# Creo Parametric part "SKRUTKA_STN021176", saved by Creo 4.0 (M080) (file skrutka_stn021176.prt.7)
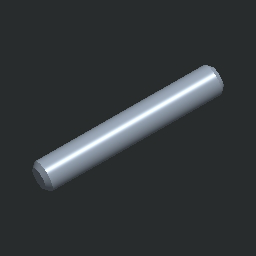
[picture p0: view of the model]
Units: millimeter Kilogram Sec (mmKs); MM, KILOGRAM, SECS
Materials in the file: OCEL_N

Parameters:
  MFG_WP_MATERIAL = "OCEL"
  NAZOV = "SKRUTKA_STN021176"
  NORMA = "STN 02 1176"
  PTC_MATERIAL_NAME = "OCEL_N"

Other parameters: HMOTNOST, HUSTOTA, D24, D14, D20

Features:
  1. datum plane "DTM2"
  2. protrusion
  3. chamfer

Other named items: BLIND, BLIND_1

Named dimensions: ezav

Layers: 1, 2, 3, 4, 5, 6, 7, 8, 9, 10, 11, 12, 13, 14, 15, 16, 17, 18, 19, 20, 21, 22, 23, 24, 25, 26, 27, 28, 29, 30, 31, 32

Family table entries: GENERIC, SKRUTKA_M3, SKRUTKA_STN021176, value(d_val), value(i_val), SKRUTKA_M4, SKRUTKA_STN021176, SKRUTKA_M5, SKRUTKA_STN021176, SKRUTKA_M6, SKRUTKA_STN021176, SKRUTKA_M8, SKRUTKA_STN021176, !/ , 2/$, SKRUTKA_M8X1, SKRUTKA_STN021176, !/ , 2/$, SKRUTKA_M10, SKRUTKA_STN021176, !/$, 2/(, SKRUTKA_M10X1_25, SKRUTKA_STN021176, !/$, 2/(, SKRUTKA_M12, SKRUTKA_STN021176, !/(, 2/., SKRUTKA_M12X1_25, SKRUTKA_STN021176, !/(, 2/., SKRUTKA_M14, SKRUTKA_STN021176, !/,, 2/2, SKRUTKA_M14X1_5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

Surfaces: 8 plane, 5 cylinder, 4 cone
